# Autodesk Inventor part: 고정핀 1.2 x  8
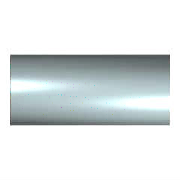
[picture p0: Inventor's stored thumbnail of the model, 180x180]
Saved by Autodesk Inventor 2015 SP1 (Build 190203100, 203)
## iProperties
IsCustomPart: 1
Created: 2012-02
Part Number: 고정핀 1.2 x  8
Material: 강철, 연강
Description: 평행 핀
Document SubType Name: Modeling
Standard: KS B 1320
Designer: P15F
Standards Organization: KS
Language: ko-KR
Size Designation: C 1.2 x  8
Categories: <MemberInstance><Categories><Category DisplayName="조임쇠" InternalName="e4da775c-781d-43d5-af7c-5136215cf5a6" Mnemonic="FSTN"><Category DisplayName="핀" InternalNa
Density: 1 g/cm^3
Appearance: 노란색
Author: P15F
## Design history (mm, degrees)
sketch "스케치1"
  geometry: C1 r 0.6 at (0, 0); 1 further point
  constraints: 1 centre point, 1 coincident
  dimensions: "d1" = 1.2 diameter of C1 (= NND)
extrude "본체" new body sketch "스케치1" distance "d2" = 8 (= NLG); taper "d3" = 0 deg
node "작업 평면1"
body "Solid1"
other parameters: "NND" = 1.2 [user parameter; used in 1 equation term], "NLG" = 8 [user parameter; used in 1 equation term], "d8" = 0, "d9" = 0, "d10" = 0
